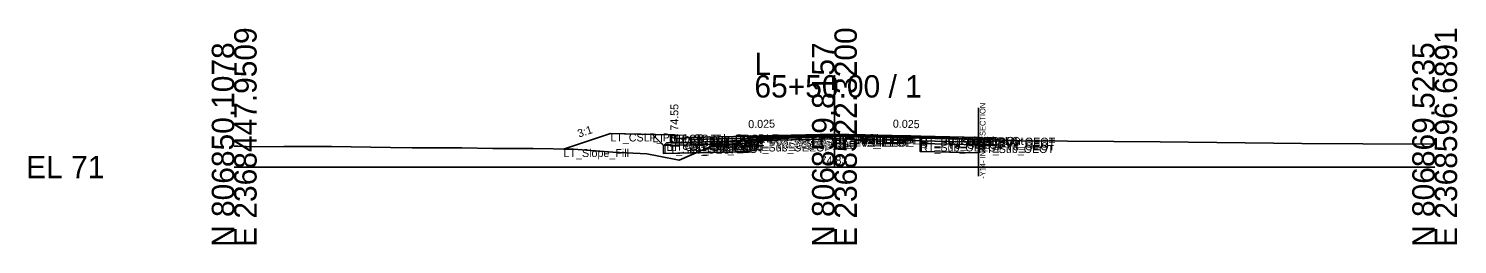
# Model space of a CAD drawing. Extents: x -26 to 8153, y -10 to 9520.
# Drawn here: x 5974.3 to 6152.8, y 5990.3 to 6017.3 of the extents above; entities that cross this region are included whole.
import ezdxf

# ---------------------------------------------------------------- set-up
doc = ezdxf.new("R2010")
doc.units = 0
for name, color, linetype in [('Exist CMT Pavement', 7, 'Continuous'), ('Exist Cross Section Cell', 7, 'Continuous'), ('Exist XS Center Line Elevation Label', 7, 'Continuous'), ('Exist XS Ground Line', 7, 'Continuous'), ('Prop CMT Conc Surface', 7, 'Continuous'), ('Prop CMT Concrete Structures', 7, 'Continuous'), ('Prop CMT Pvmt Course 1', 7, 'Continuous'), ('Prop CMT Pvmt Course 1 CG', 7, 'Continuous'), ('Prop CMT Pvmt Course 1 Wedge', 7, 'Continuous'), ('Prop CMT Pvmt Course 2', 7, 'Continuous'), ('Prop CMT Pvmt Course 2 Wedge', 7, 'Continuous'), ('Prop CMT Pvmt Course 3', 7, 'Continuous'), ('Prop CMT Pvmt Course 3 Wedge', 7, 'Continuous'), ('Prop CMT Pvmt Surface', 7, 'Continuous'), ('Prop CMT Pvmt Wedge Surface 1', 7, 'Continuous'), ('Prop CMT Pvmt Wedge Surface 2', 7, 'Continuous'), ('Prop CMT Pvmt Wedge Surface 3', 7, 'Continuous'), ('Prop CMT Shallow Undercut', 7, 'Continuous'), ('Prop CMT Shallow Undercut Boundary', 7, 'Continuous'), ('Prop CMT Shear Line', 7, 'Continuous'), ('Prop CMT Slope Grass', 7, 'Continuous'), ('Prop CMT Subgrade Earthwork', 7, 'Continuous'), ('Prop XS Earthwork Shape', 7, 'Continuous'), ('Prop XS Hydro Elevations', 7, 'Continuous'), ('Prop XS SE Text', 7, 'Continuous'), ('Prop XS Side Slope Text', 7, 'Continuous'), ('Prop XS Subgrade Earthwork', 7, 'Continuous'), ('Scratch_Level_2', 7, 'Continuous'), ('Scratch_Level_6', 7, 'Continuous')]:
    doc.layers.add(name, color=color, linetype=linetype)

msp = doc.modelspace()

# ---------------------------------------------------------------- linework, layer by layer
at = {"layer": 'Exist CMT Pavement'}
for p, q in [((6064.46, 6003.42), (6071.2, 6003.69)), ((6071.2, 6003.69), (6074.71, 6003.83)), ((6074.71, 6003.83), (6078.44, 6003.8)), ((6078.44, 6003.8), (6085.71, 6003.77))]:
    msp.add_line(p, q, dxfattribs=at)
at = {"layer": 'Exist Cross Section Cell'}
for p, q in [((6075, 6000), (6075, 6011.5)), ((6000, 6000), (6075, 6000)), ((6075, 6000), (6150, 6000))]:
    msp.add_line(p, q, dxfattribs=at)
at = {"layer": 'Exist XS Ground Line'}
for p, q in [((6000, 6002.6), (6000.45, 6002.6)), ((6000.45, 6002.6), (6002.53, 6002.54)), ((6002.53, 6002.54), (6006.21, 6002.57)), ((6006.21, 6002.57), (6010.31, 6002.57)), ((6010.31, 6002.57), (6011.5, 6002.57)), ((6011.5, 6002.57), (6012.16, 6002.57)), ((6012.16, 6002.57), (6019.53, 6002.43)), ((6019.53, 6002.43), (6022.24, 6002.4)), ((6022.24, 6002.4), (6028.45, 6002.39)), ((6028.45, 6002.39), (6032.33, 6002.32)), ((6032.33, 6002.32), (6037.37, 6002.3)), ((6037.37, 6002.3), (6042.41, 6002.23)), ((6058.07, 6001.93), (6060.95, 6003.13)), ((6060.95, 6003.13), (6062.5, 6003.31)), ((6062.5, 6003.31), (6064.46, 6003.42)), ((6064.46, 6003.42), (6071.2, 6003.69)), ((6071.2, 6003.69), (6074.71, 6003.83)), ((6074.71, 6003.83), (6078.44, 6003.8)), ((6078.44, 6003.8), (6085.71, 6003.77)), ((6085.71, 6003.77), (6086.97, 6003.65)), ((6086.97, 6003.65), (6088.37, 6003.64)), ((6088.37, 6003.64), (6095.87, 6003.37)), ((6095.87, 6003.37), (6098.33, 6003.28)), ((6098.33, 6003.28), (6115.69, 6003.14)), ((6115.69, 6003.14), (6133.4, 6002.94)), ((6133.4, 6002.94), (6148.64, 6002.88)), ((6148.64, 6002.88), (6150, 6002.89)), ((6042.41, 6002.23), (6047.3, 6001.87)), ((6047.3, 6001.87), (6051.56, 6001.64)), ((6051.56, 6001.64), (6053.05, 6001.38)), ((6053.05, 6001.38), (6055.59, 6000.86)), ((6055.59, 6000.86), (6058.07, 6001.93))]:
    msp.add_line(p, q, dxfattribs=at)
at = {"layer": 'Prop CMT Conc Surface'}
for points in [[(6055, 6003.55), (6055, 6004.05), (6054.5, 6004.05)], [(6057, 6003.68), (6055, 6003.55)]]:
    msp.add_lwpolyline(points, dxfattribs=at)
at = {"layer": 'Prop CMT Concrete Structures'}
for points in [[(6057, 6003.68), (6055, 6003.55), (6055, 6004.05), (6054.5, 6004.05)], [(6054.5, 6004.05), (6054.5, 6003.03), (6057, 6003.09)], [(6057, 6003.09), (6057, 6003.68)]]:
    msp.add_lwpolyline(points, dxfattribs=at)
at = {"layer": 'Prop CMT Pvmt Course 1'}
for points in [[(6075, 6004.13), (6057, 6003.68)], [(6075, 6003.88), (6075, 6004.13)], [(6075, 6004.13), (6093, 6003.68)], [(6075, 6003.88), (6075, 6004.13)], [(6057, 6003.68), (6057, 6003.43)], [(6057, 6003.43), (6064.46, 6003.61)], [(6064.46, 6003.74), (6075, 6004)], [(6064.46, 6003.61), (6064.46, 6003.74)], [(6075, 6004), (6075, 6003.88), (6075, 6003.88)], [(6085.71, 6003.73), (6075, 6004)], [(6075, 6004), (6075, 6003.88), (6075, 6003.88)], [(6085.71, 6003.61), (6085.71, 6003.73)], [(6093, 6003.43), (6085.71, 6003.61)], [(6093, 6003.68), (6093, 6003.43)]]:
    msp.add_lwpolyline(points, dxfattribs=at)
at = {"layer": 'Prop CMT Pvmt Course 1 CG'}
for points in [[(6057, 6003.09), (6054, 6003.02), (6053.66, 6002.68)], [(6053.66, 6002.68), (6057, 6002.76)], [(6057, 6002.76), (6057, 6003.09)]]:
    msp.add_lwpolyline(points, dxfattribs=at)
at = {"layer": 'Prop CMT Pvmt Course 1 Wedge'}
for points in [[(6075, 6004), (6064.46, 6003.74)], [(6075, 6004), (6085.71, 6003.73)]]:
    msp.add_lwpolyline(points, dxfattribs=at)
at = {"layer": 'Prop CMT Pvmt Course 2'}
for points in [[(6064.46, 6003.61), (6057, 6003.43)], [(6057, 6003.43), (6057, 6003.1)], [(6057, 6003.1), (6064.46, 6003.28)], [(6064.46, 6003.28), (6064.46, 6003.61)], [(6085.71, 6003.28), (6085.71, 6003.61)], [(6085.71, 6003.61), (6093, 6003.43)], [(6093, 6003.1), (6085.71, 6003.28)], [(6093, 6003.43), (6093, 6003.1)]]:
    msp.add_lwpolyline(points, dxfattribs=at)
at = {"layer": 'Prop CMT Pvmt Course 2 Wedge'}
for points in [[(6075, 6003.88), (6064.46, 6003.61)], [(6075, 6003.88), (6085.71, 6003.61)]]:
    msp.add_lwpolyline(points, dxfattribs=at)
at = {"layer": 'Prop CMT Pvmt Course 3'}
for points in [[(6064.46, 6003.28), (6057, 6003.1)], [(6057, 6003.1), (6057, 6002.76)], [(6057, 6002.76), (6064.46, 6002.95)], [(6064.46, 6002.95), (6064.46, 6003.28)], [(6085.71, 6003.28), (6093, 6003.1)], [(6085.71, 6002.95), (6085.71, 6003.28)], [(6093, 6002.76), (6085.71, 6002.95)], [(6093, 6003.1), (6093, 6002.76)]]:
    msp.add_lwpolyline(points, dxfattribs=at)
at = {"layer": 'Prop CMT Pvmt Course 3 Wedge'}
for points in [[(6075, 6003.55), (6064.46, 6003.28)], [(6075, 6003.55), (6085.71, 6003.28)]]:
    msp.add_lwpolyline(points, dxfattribs=at)
at = {"layer": 'Prop CMT Pvmt Surface'}
for points in [[(6075, 6004.13), (6057, 6003.68)], [(6075, 6004.13), (6093, 6003.68), (6093, 6003.48)]]:
    msp.add_lwpolyline(points, dxfattribs=at)
at = {"layer": 'Prop CMT Pvmt Wedge Surface 1'}
for points in [[(6057, 6003.43), (6057, 6003.68)], [(6064.46, 6003.61), (6057, 6003.43)], [(6075, 6004), (6064.46, 6003.74)], [(6064.46, 6003.74), (6064.46, 6003.61)], [(6075, 6004), (6085.71, 6003.73)], [(6085.71, 6003.73), (6085.71, 6003.61)], [(6085.71, 6003.61), (6093, 6003.43)], [(6093, 6003.43), (6093, 6003.68)]]:
    msp.add_lwpolyline(points, dxfattribs=at)
at = {"layer": 'Prop CMT Pvmt Wedge Surface 2'}
for points in [[(6075, 6003.88), (6057, 6003.43)], [(6057, 6003.43), (6057, 6003.68)], [(6075, 6003.88), (6093, 6003.43)], [(6093, 6003.43), (6093, 6003.68)]]:
    msp.add_lwpolyline(points, dxfattribs=at)
at = {"layer": 'Prop CMT Pvmt Wedge Surface 3'}
for points in [[(6057, 6003.1), (6057, 6003.68)], [(6075, 6003.55), (6057, 6003.1)], [(6075, 6003.55), (6093, 6003.1)], [(6093, 6003.1), (6093, 6003.68)]]:
    msp.add_lwpolyline(points, dxfattribs=at)
at = {"layer": 'Prop CMT Shallow Undercut'}
for p, q in [((6093, 6002.76), (6085.71, 6002.95)), ((6085.71, 6002.95), (6085.71, 6001.95)), ((6093, 6001.76), (6093, 6002.76)), ((6085.71, 6001.95), (6093, 6001.76))]:
    msp.add_line(p, q, dxfattribs=at)
msp.add_lwpolyline([(6057.72, 6001.78), (6058.07, 6001.93), (6060.26, 6002.85), (6064.46, 6002.95), (6064.46, 6001.95)], close=True, dxfattribs=at)
at = {"layer": 'Prop CMT Shallow Undercut Boundary'}
for p, q in [((6053.66, 6002.68), (6053.66, 6001.68)), ((6064.46, 6002.95), (6064.46, 6001.95)), ((6085.71, 6002.95), (6085.71, 6001.95)), ((6093, 6002.76), (6093, 6001.76)), ((6053.66, 6001.68), (6064.46, 6001.95)), ((6093, 6001.76), (6085.71, 6001.95))]:
    msp.add_line(p, q, dxfattribs=at)
at = {"layer": 'Prop CMT Shear Line'}
msp.add_line((6093, 5998.85), (6093, 6007.42), dxfattribs=at)
at = {"layer": 'Prop CMT Slope Grass'}
msp.add_lwpolyline([(6054.5, 6004.05), (6047, 6004.2), (6041.15, 6002.25)], dxfattribs=at)
at = {"layer": 'Prop CMT Subgrade Earthwork'}
for points in [[(6057, 6002.76), (6053.66, 6002.68), (6052.25, 6004.09)], [(6064.46, 6002.95), (6057, 6002.76)], [(6064.46, 6002.95), (6064.46, 6003.42)], [(6085.71, 6002.95), (6085.71, 6003.77)], [(6085.71, 6002.95), (6093, 6002.76)]]:
    msp.add_lwpolyline(points, dxfattribs=at)
at = {"layer": 'Prop XS Earthwork Shape'}
for points in [[(6053.66, 6001.68), (6057.72, 6001.78), (6055.59, 6000.86), (6053.05, 6001.38), (6051.56, 6001.64), (6047.3, 6001.87), (6042.41, 6002.23), (6041.15, 6002.25), (6047, 6004.2), (6052.25, 6004.09), (6053.66, 6002.68)], [(6057.72, 6001.78), (6058.07, 6001.93), (6060.26, 6002.85), (6057, 6002.76), (6053.66, 6002.68), (6053.66, 6001.68)], [(6057.72, 6001.78), (6064.46, 6001.95), (6064.46, 6002.95), (6060.26, 6002.85), (6058.07, 6001.93)], [(6060.26, 6002.85), (6060.95, 6003.13), (6062.5, 6003.31), (6064.46, 6003.42), (6064.46, 6002.95)], [(6093, 6001.76), (6085.71, 6001.95), (6085.71, 6002.95), (6093, 6002.76)]]:
    msp.add_lwpolyline(points, close=True, dxfattribs=at)
at = {"layer": 'Prop XS Subgrade Earthwork'}
for p, q in [((6053.66, 6002.68), (6064.46, 6002.95)), ((6085.71, 6002.95), (6093, 6002.76))]:
    msp.add_line(p, q, dxfattribs=at)
at = {"layer": 'Scratch_Level_6'}
for p, q in [((6093, 6002.76), (6085.71, 6002.95)), ((6085.71, 6002.95), (6085.71, 6001.95)), ((6093, 6001.76), (6093, 6002.76)), ((6085.71, 6001.95), (6093, 6001.76))]:
    msp.add_line(p, q, dxfattribs=at)
msp.add_lwpolyline([(6057.72, 6001.78), (6058.07, 6001.93), (6060.26, 6002.85), (6064.46, 6002.95), (6064.46, 6001.95)], close=True, dxfattribs=at)

# ---------------------------------------------------------------- texts
at = {"layer": 'Exist Cross Section Cell'}
for s, p in [('E 2368447.9509', (6002.8, 5990)), ('E 2368522.3200', (6077.8, 5990)), ('E 2368596.6891', (6152.8, 5990)), ('N 806850.1078', (6000, 5990)), ('N 806859.8157', (6075, 5990)), ('N 806869.5235', (6150, 5990))]:
    msp.add_text(s, height=2.8, rotation=90, dxfattribs=at).set_placement(p)
for s, p in [('L', (6065, 6011.5)), ('65+50.00 / 1', (6065, 6008.7)), ('EL 71', (5974, 5998.6))]:
    msp.add_text(s, height=2.8, dxfattribs=at).set_placement(p)
at = {"layer": 'Exist XS Center Line Elevation Label'}
msp.add_text('74.83', height=1, dxfattribs=at).set_placement((6073.27, 6000.33))
at = {"layer": 'Prop CMT Shear Line'}
msp.add_text('-Y14- INTERSECTION', height=0.7, rotation=90, dxfattribs=at).set_placement((6093.87, 5998.53))
at = {"layer": 'Prop XS Hydro Elevations'}
msp.add_text('74.55', height=1, rotation=90, dxfattribs=at).set_placement((6055.5, 6004.55))
at = {"layer": 'Prop XS SE Text'}
for rotation, p in [(1.4321, (6064.24, 6004.86)), (358.5679, (6082.29, 6004.94))]:
    msp.add_text('0.025', height=1, rotation=rotation, dxfattribs=at).set_placement(p)
at = {"layer": 'Prop XS Side Slope Text'}
msp.add_text('3:1', height=1, rotation=18.4349, dxfattribs=at).set_placement((6043.08, 6003.68))
at = {"layer": 'Scratch_Level_2'}
for s, p in [('LT_CSLP_Pnt', (6047, 6003.2)), ('LT_Sub_Trench_Out_DLT', (6052.25, 6003.09)), ('LT_CG_Top_BOC', (6054.5, 6003.05)), ('LT_CG_Top_Face', (6055, 6003.05)), ('PV1_PGL', (6075, 6003.13)), ('LT_Slope_Fill', (6041.15, 6001.25)), ('LT_Sub_OEOP', (6053.66, 6001.68)), ('LT_CG1_Shelf_Out', (6054, 6002.02)), ('LT_CG_Bot_BOC', (6054.5, 6002.03)), ('LT_CG_Top_Gut', (6055, 6002.55)), ('LT_PV1_OEOT', (6057, 6002.68)), ('LT_PV2_OEOT', (6057, 6002.43)), ('LT_PV3_OEOT', (6057, 6002.1)), ('LT_CG_Bot_IE', (6057, 6002.09)), ('LT_Sub_OEOT', (6057, 6001.76)), ('LT_PV1_OEEOP', (6064.46, 6002.74)), ('LT_PV2_OEEOP', (6064.46, 6002.61)), ('LT_PV_OEEOP_EG', (6064.46, 6002.42)), ('LT_PV3_OEEOP', (6064.46, 6002.28)), ('LT_Sub_OEEOP', (6064.46, 6001.95)), ('LT_PV_Sub_Tie_Out', (6064.48, 6002.42)), ('RT_PV1_IEEOP', (6075, 6003)), ('LT_PV1_IEEOP', (6075, 6003)), ('RT_PV2_IEEOP', (6075, 6002.88)), ('LT_PV2_IEEOP', (6075, 6002.88)), ('PV2_PGL', (6075, 6002.88)), ('RT_PV_IEEOP_EG', (6075, 6002.83)), ('LT_PV_IEEOP_EG', (6075, 6002.83)), ('RT_PV3_IEEOP', (6075, 6002.55)), ('LT_PV3_IEEOP', (6075, 6002.55)), ('RT_PV_Sub_Tie_Out', (6085.7, 6002.77)), ('RT_PV_OEEOP_EG', (6085.71, 6002.77)), ('RT_PV1_OEEOP', (6085.71, 6002.73)), ('RT_PV2_OEEOP', (6085.71, 6002.61)), ('RT_PV3_OEEOP', (6085.71, 6002.28)), ('RT_Sub_OEEOP', (6085.71, 6001.95)), ('RT_PV1_OEOT', (6093, 6002.68)), ('RT_PV2_OEOT', (6093, 6002.43)), ('RT_PV3_OEOT', (6093, 6002.1)), ('RT_Sub_OEOT', (6093, 6001.76))]:
    msp.add_text(s, height=1, dxfattribs=at).set_placement(p)

doc.saveas('drawing.dxf')
